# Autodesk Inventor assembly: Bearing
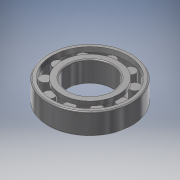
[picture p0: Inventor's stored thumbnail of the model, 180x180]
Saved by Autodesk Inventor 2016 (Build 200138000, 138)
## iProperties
Created: 2015-08
Part Number: Bearing
Document SubType Name: Assembly
Designer: Ugljesa
Mass: 72.9462 g
Surface Area: 85.1408 cm^2
Volume: 9.29251 cm^3
Density: 7.85 g/cm^3
ClientObjectVersion: 1
Author: Ugljesa
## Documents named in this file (2)
- C:\Users\Ugljesa\Desktop\Turbokompr\Assembly1\Design Accelerator\Bearing1.iam
- C:\Users\Ugljesa\Documents\Inventor\Content Center Files\R2016\en-US\BS 292 (V)\BS 292_ Part 1 - N 1005 - 25 x 47 x 12.ipt
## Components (1 placed, 1 different names)
1. BS 292: Part 1 (V) (Metric) N 1005 - 25 x 47 x 12:1
